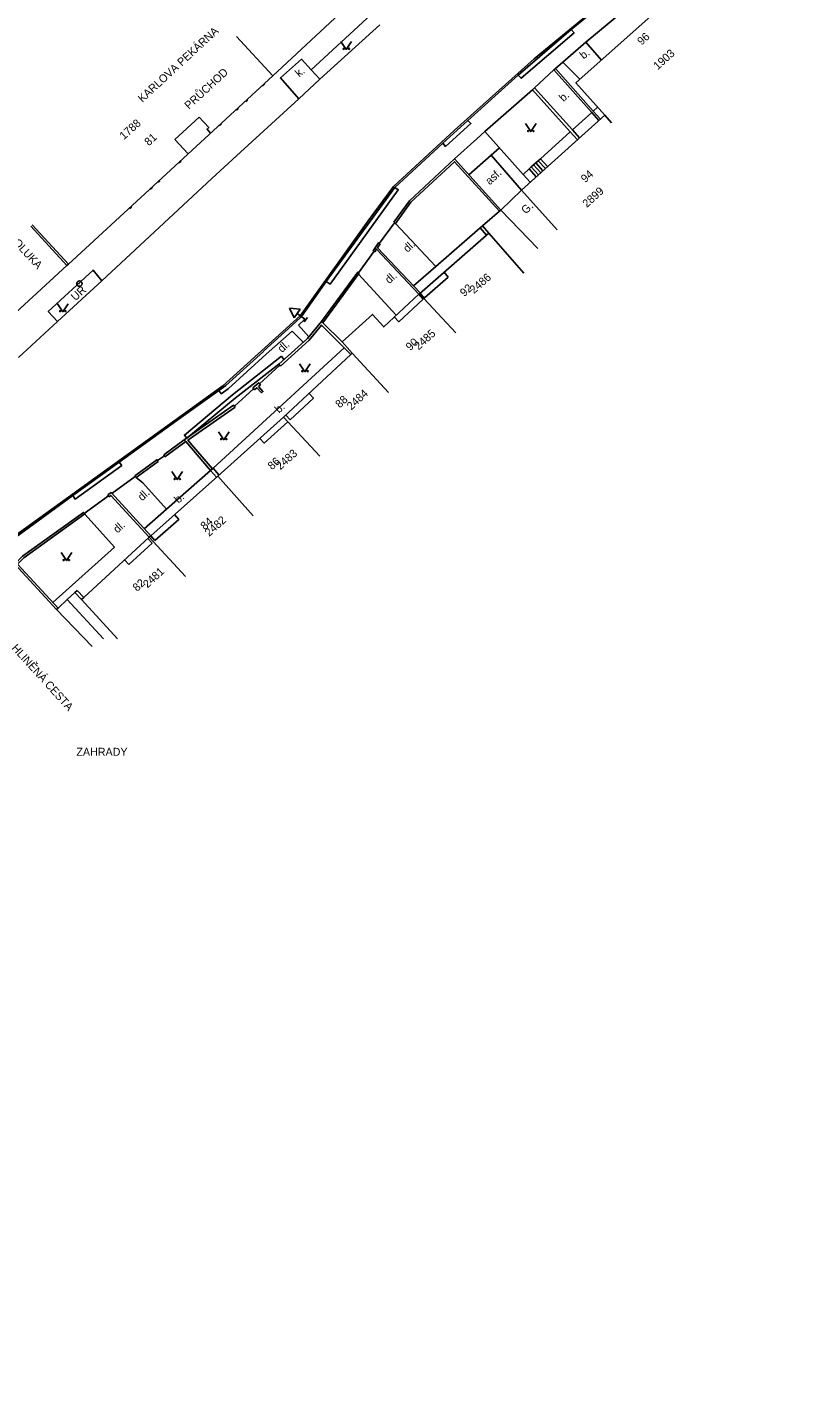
# Model space of a CAD drawing. Extents: x -584400 to -581602, y -1210894 to -1208793.
# Drawn here: x -582319.7 to -582247, y -1209460.2 to -1209333 of the extents above; entities that cross this region are included whole.
import ezdxf

# ---------------------------------------------------------------- set-up
doc = ezdxf.new("R2010")
doc.units = 0
for name, color, linetype in [('BUDOVY_MĚŘ', 7, 'Continuous'), ('POMOC_POPIS', 7, 'Continuous'), ('ROZHRANÍ_PLOCH', 7, 'Continuous'), ('ZN_DOPLŇKOVÉ', 7, 'Continuous'), ('ZN_KULTUR', 7, 'Continuous'), ('Č_POPIS_EVID', 7, 'Continuous')]:
    doc.layers.add(name, color=color, linetype=linetype)

msp = doc.modelspace()

# ---------------------------------------------------------------- linework, layer by layer
at = {"layer": 'BUDOVY_MĚŘ'}
for points in [[(-582265.6, -1209341.22), (-582268.3, -1209338.21), (-582257.05, -1209328.13), (-582254.27, -1209331.2)], [(-582287.76, -1209329.21), (-582296.71, -1209337.53)], [(-582300.1, -1209333.85), (-582296.71, -1209337.53)], [(-582296.71, -1209337.53), (-582315.86, -1209355.19)], [(-582265.6, -1209341.22), (-582273.4, -1209348.25)], [(-582264.96, -1209341.94), (-582265.6, -1209341.22)], [(-582271.88, -1209353.72), (-582275.35, -1209350.12), (-582273.4, -1209348.25)], [(-582270.06, -1209351.97), (-582273.4, -1209348.25)], [(-582319.25, -1209351.51), (-582315.86, -1209355.19)], [(-582273.18, -1209356.05), (-582276.47, -1209352.28), (-582282.96, -1209357.96)], [(-582282.96, -1209357.96), (-582283.03, -1209358.02), (-582286.31, -1209361.07), (-582287.36, -1209359.9), (-582290.22, -1209362.48)], [(-582279.57, -1209361.63), (-582282.96, -1209357.96)], [(-582289.26, -1209363.55), (-582290.22, -1209362.48)], [(-582295.7, -1209369.52), (-582289.38, -1209363.66), (-582289.26, -1209363.55)], [(-582285.86, -1209367.21), (-582289.26, -1209363.55)], [(-582301.87, -1209375.05), (-582295.7, -1209369.52)], [(-582292.3, -1209373.19), (-582295.7, -1209369.52)], [(-582308.29, -1209380.79), (-582308.15, -1209380.66), (-582301.87, -1209375.05)], [(-582301.87, -1209375.05), (-582298.54, -1209378.77)], [(-582308.29, -1209380.79), (-582314.42, -1209386.44), (-582314.64, -1209386.64)], [(-582304.9, -1209384.46), (-582308.29, -1209380.79)], [(-582311.25, -1209390.32), (-582314.64, -1209386.64)]]:
    msp.add_lwpolyline(points, dxfattribs=at)
at = {"layer": 'ROZHRANÍ_PLOCH'}
for points in [[(-582411.27, -1209460.15), (-582406.62, -1209456.16), (-582403.59, -1209453.59), (-582391.95, -1209443.5), (-582374.01, -1209428.06), (-582365.14, -1209420.28), (-582352.37, -1209408.95), (-582339.06, -1209397), (-582326.13, -1209385.36), (-582321.21, -1209380.9), (-582313.38, -1209375.25), (-582301.4, -1209366.6), (-582294.11, -1209360), (-582287.76, -1209351.14), (-582285.39, -1209347.91), (-582279.69, -1209342.63), (-582272.21, -1209335.94), (-582264.86, -1209329.84), (-582259.42, -1209325.45), (-582254.82, -1209321.63), (-582249.41, -1209317.62), (-582247.49, -1209316.56)], [(-582268.74, -1209333.19), (-582254.73, -1209321.75), (-582249.32, -1209317.74), (-582247.41, -1209316.69), (-582247.04, -1209316.55)], [(-582258.44, -1209326.96), (-582267.37, -1209334.39)], [(-582287.5, -1209331.8), (-582293.1, -1209336.97)], [(-582286.68, -1209332.75), (-582292.29, -1209337.84)], [(-582273.71, -1209337.48), (-582273.44, -1209337.76), (-582268.48, -1209333.51), (-582268.74, -1209333.19)], [(-582268.74, -1209333.19), (-582273.71, -1209337.48)], [(-582269.54, -1209336.27), (-582267.37, -1209334.39)], [(-582265.92, -1209336.08), (-582267.37, -1209334.39)], [(-582293.1, -1209336.97), (-582294.01, -1209335.98), (-582295.99, -1209337.74), (-582294.28, -1209339.69)], [(-582270.21, -1209336.85), (-582269.54, -1209336.27)], [(-582267.92, -1209337.87), (-582269.54, -1209336.27)], [(-582293.1, -1209336.97), (-582292.29, -1209337.84)], [(-582278.43, -1209341.72), (-582273.71, -1209337.48)], [(-582270.36, -1209336.97), (-582272.18, -1209338.67)], [(-582270.21, -1209336.85), (-582270.36, -1209336.97)], [(-582266.82, -1209340.97), (-582270.36, -1209336.97)], [(-582266.68, -1209340.84), (-582270.21, -1209336.85)], [(-582297.7, -1209338.45), (-582297.66, -1209338.5)], [(-582297.56, -1209338.31), (-582297.51, -1209338.36), (-582297.66, -1209338.5)], [(-582292.29, -1209337.84), (-582294.28, -1209339.69)], [(-582272.37, -1209338.84), (-582276.84, -1209342.75)], [(-582272.37, -1209338.84), (-582272.18, -1209338.67)], [(-582268.83, -1209342.78), (-582272.37, -1209338.84)], [(-582268.64, -1209342.61), (-582272.18, -1209338.67)], [(-582294.28, -1209339.69), (-582300.1, -1209345.03), (-582302.43, -1209347.16), (-582312.73, -1209356.74)], [(-582299.28, -1209339.9), (-582299.23, -1209339.95)], [(-582299.13, -1209339.77), (-582299.09, -1209339.82), (-582299.23, -1209339.95)], [(-582303.6, -1209341.42), (-582305.88, -1209343.51), (-582304.65, -1209344.85)], [(-582303.6, -1209341.42), (-582302.71, -1209342.38), (-582302.87, -1209342.53), (-582302.53, -1209342.9)], [(-582300.15, -1209340.71), (-582300.11, -1209340.76)], [(-582300.01, -1209340.57), (-582299.96, -1209340.62), (-582300.11, -1209340.76)], [(-582266.82, -1209340.97), (-582268.64, -1209342.61)], [(-582266.15, -1209341.72), (-582266.82, -1209340.97)], [(-582266.27, -1209340.48), (-582266.68, -1209340.84)], [(-582266.01, -1209341.59), (-582266.68, -1209340.84)], [(-582301.74, -1209342.17), (-582301.69, -1209342.22)], [(-582301.59, -1209342.03), (-582301.54, -1209342.08), (-582301.69, -1209342.22)], [(-582278.43, -1209341.72), (-582280.77, -1209343.86)], [(-582280.77, -1209343.86), (-582280.51, -1209344.15), (-582278.15, -1209342), (-582278.43, -1209341.72)], [(-582277.58, -1209343.45), (-582276.84, -1209342.75)], [(-582276.84, -1209342.75), (-582273.26, -1209346.78)], [(-582268.83, -1209342.78), (-582271.63, -1209345.31)], [(-582268.16, -1209343.53), (-582268.83, -1209342.78)], [(-582267.97, -1209343.35), (-582268.64, -1209342.61)], [(-582285.27, -1209348), (-582280.77, -1209343.86)], [(-582277.58, -1209343.45), (-582279.68, -1209345.33)], [(-582278.34, -1209346.82), (-582275.47, -1209344.3)], [(-582273.4, -1209348.25), (-582276.25, -1209344.98)], [(-582271.63, -1209345.31), (-582271.84, -1209345.5)], [(-582270.96, -1209346.05), (-582271.63, -1209345.31)], [(-582305.51, -1209345.65), (-582305.47, -1209345.7)], [(-582305.37, -1209345.51), (-582305.32, -1209345.56), (-582305.47, -1209345.7)], [(-582272.69, -1209346.26), (-582273.26, -1209346.78)], [(-582272.49, -1209346.08), (-582272.69, -1209346.26)], [(-582272.02, -1209347), (-582272.69, -1209346.26)], [(-582272.27, -1209345.88), (-582272.49, -1209346.08)], [(-582271.82, -1209346.82), (-582272.49, -1209346.08)], [(-582272.06, -1209345.69), (-582272.27, -1209345.88)], [(-582271.6, -1209346.63), (-582272.27, -1209345.88)], [(-582271.84, -1209345.5), (-582272.06, -1209345.69)], [(-582271.39, -1209346.44), (-582272.06, -1209345.69)], [(-582271.17, -1209346.24), (-582271.84, -1209345.5)], [(-582307.49, -1209347.47), (-582307.44, -1209347.52)], [(-582307.34, -1209347.34), (-582307.3, -1209347.39), (-582307.44, -1209347.52)], [(-582273.26, -1209346.78), (-582272.6, -1209347.52)], [(-582308.2, -1209348.13), (-582308.16, -1209348.18)], [(-582308.06, -1209347.99), (-582308.01, -1209348.05), (-582308.16, -1209348.18)], [(-582291.7, -1209356.83), (-582291.34, -1209357.07), (-582284.95, -1209348.22), (-582285.27, -1209348)], [(-582285.27, -1209348), (-582291.7, -1209356.83)], [(-582310.15, -1209349.92), (-582310.1, -1209349.98)], [(-582310.01, -1209349.79), (-582309.96, -1209349.84), (-582310.1, -1209349.98)], [(-582275.48, -1209350.24), (-582277.07, -1209351.59)], [(-582285.22, -1209351.37), (-582281.44, -1209355.41)], [(-582277.29, -1209351.78), (-582277.07, -1209351.59)], [(-582276.47, -1209352.28), (-582277.07, -1209351.59)], [(-582281.44, -1209355.41), (-582277.29, -1209351.78)], [(-582276.68, -1209352.47), (-582277.29, -1209351.78)], [(-582316, -1209355.31), (-582320.8, -1209359.72)], [(-582283.52, -1209357.23), (-582281.44, -1209355.41)], [(-582312.73, -1209356.74), (-582313.55, -1209355.75), (-582317.75, -1209359.62), (-582316.89, -1209360.58)], [(-582312.73, -1209356.74), (-582316.89, -1209360.58)], [(-582288.67, -1209356.13), (-582285.15, -1209359.98)], [(-582280.26, -1209356.41), (-582282.49, -1209358.36), (-582282.89, -1209357.9)], [(-582280.26, -1209356.41), (-582280.66, -1209355.95)], [(-582294.01, -1209360.11), (-582291.7, -1209356.83)], [(-582282.61, -1209358.46), (-582283.03, -1209358.02)], [(-582282.61, -1209358.46), (-582284.9, -1209360.59), (-582285.32, -1209360.14)], [(-582316.89, -1209360.58), (-582320.52, -1209363.93)], [(-582297.58, -1209363.36), (-582294.57, -1209360.62), (-582294.01, -1209360.11)], [(-582294.3, -1209360.91), (-582293.73, -1209360.39), (-582294.01, -1209360.11)], [(-582297.32, -1209363.63), (-582294.89, -1209361.47)], [(-582293.87, -1209362.52), (-582294.89, -1209361.47)], [(-582294.3, -1209360.91), (-582293.33, -1209361.99)], [(-582302.31, -1209374.3), (-582290.01, -1209363.03)], [(-582304.77, -1209371.49), (-582304.99, -1209371.21), (-582300.47, -1209367.43), (-582295.9, -1209363.82)], [(-582301.76, -1209367.04), (-582301.12, -1209366.57), (-582297.58, -1209363.38)], [(-582297.32, -1209363.63), (-582300.89, -1209366.89)], [(-582295.66, -1209364.13), (-582295.9, -1209363.82)], [(-582304.77, -1209371.49), (-582300.23, -1209367.75), (-582296.14, -1209364.57)], [(-582301.76, -1209367.04), (-582301.53, -1209367.34), (-582300.89, -1209366.89)], [(-582311.09, -1209373.74), (-582305.7, -1209369.85), (-582301.76, -1209367.04)], [(-582295.09, -1209369.77), (-582292.9, -1209367.75), (-582293.31, -1209367.31)], [(-582295.09, -1209369.77), (-582295.5, -1209369.34)], [(-582295.29, -1209369.97), (-582297.53, -1209371.97), (-582297.93, -1209371.52)], [(-582311.09, -1209373.74), (-582315.45, -1209376.88)], [(-582315.45, -1209376.88), (-582315.23, -1209377.21), (-582310.86, -1209374.06)], [(-582311.09, -1209373.74), (-582310.86, -1209374.06)], [(-582306.68, -1209378.15), (-582302.56, -1209374.52)], [(-582302.56, -1209374.52), (-582302.31, -1209374.3)], [(-582301.99, -1209375.15), (-582302.56, -1209374.52)], [(-582301.75, -1209374.94), (-582302.31, -1209374.3)], [(-582309.52, -1209375.19), (-582308.9, -1209375.69), (-582306.68, -1209378.15)], [(-582325.08, -1209384.63), (-582321.12, -1209381.02), (-582315.45, -1209376.88)], [(-582306.68, -1209378.15), (-582308.77, -1209379.99)], [(-582317.31, -1209386.9), (-582311.55, -1209381.71), (-582314.29, -1209378.66)], [(-582307.75, -1209381.11), (-582305.52, -1209379.12), (-582305.92, -1209378.67)], [(-582310.19, -1209383.36), (-582308.02, -1209381.35), (-582308.42, -1209380.91)], [(-582307.75, -1209381.11), (-582308.15, -1209380.66)], [(-582310.19, -1209383.36), (-582310.6, -1209382.92)], [(-582312.57, -1209390.31), (-582315.97, -1209386.64)]]:
    msp.add_lwpolyline(points, dxfattribs=at)
at = {"layer": 'ZN_DOPLŇKOVÉ'}
for p, q in [((-582295.13, -1209359.31), (-582294.72, -1209360.22)), ((-582295.13, -1209359.31), (-582294.14, -1209359.41)), ((-582294.72, -1209360.22), (-582294.14, -1209359.41)), ((-582293.62, -1209360.4), (-582294.43, -1209359.82)), ((-582293.77, -1209360.6), (-582293.47, -1209360.2))]:
    msp.add_line(p, q, dxfattribs=at)
for points in [[(-582285.37, -1209351.26), (-582283.9, -1209349.26), (-582279.68, -1209345.33), (-582275.35, -1209350.12)], [(-582275.48, -1209350.24), (-582279.69, -1209345.59), (-582283.77, -1209349.38), (-582285.22, -1209351.37)], [(-582275.48, -1209350.24), (-582275.35, -1209350.12)], [(-582316, -1209355.31), (-582319.38, -1209351.64)], [(-582285.29, -1209351.32), (-582286.72, -1209353.24)], [(-582285.37, -1209351.26), (-582285.22, -1209351.37)], [(-582287.22, -1209353.99), (-582288.68, -1209356)], [(-582287.12, -1209353.67), (-582287.3, -1209353.94), (-582287.15, -1209354.04)], [(-582287.15, -1209354.04), (-582286.99, -1209353.8)], [(-582286.99, -1209353.8), (-582287.12, -1209353.67), (-582286.8, -1209353.19), (-582286.65, -1209353.29)], [(-582283.03, -1209358.02), (-582286.99, -1209353.8)], [(-582286.65, -1209353.29), (-582286.89, -1209353.65), (-582282.9, -1209357.89)], [(-582316, -1209355.31), (-582315.86, -1209355.19)], [(-582292.14, -1209360.56), (-582288.75, -1209355.95), (-582288.61, -1209356.05)], [(-582288.61, -1209356.05), (-582292.01, -1209360.69)], [(-582296.14, -1209364.57), (-582293.47, -1209362.16), (-582292.14, -1209360.56), (-582292.01, -1209360.69)], [(-582289.38, -1209363.66), (-582292.13, -1209360.91), (-582293.3, -1209362.33), (-582295.98, -1209364.74)], [(-582292.01, -1209360.69), (-582290.22, -1209362.48)], [(-582296.06, -1209364.66), (-582297.95, -1209366.4)], [(-582296.14, -1209364.57), (-582295.98, -1209364.74)], [(-582298.51, -1209366.89), (-582300.31, -1209368.51)], [(-582298.59, -1209366.8), (-582298.03, -1209366.31), (-582297.87, -1209366.49)], [(-582298.59, -1209366.8), (-582298.43, -1209366.98)], [(-582297.77, -1209367.26), (-582298.2, -1209366.77), (-582298.43, -1209366.98)], [(-582297.87, -1209366.49), (-582298.06, -1209366.65)], [(-582298.06, -1209366.65), (-582297.63, -1209367.13), (-582297.77, -1209367.26)], [(-582304.87, -1209371.82), (-582305.01, -1209371.66), (-582300.38, -1209368.41), (-582300.24, -1209368.6)], [(-582300.24, -1209368.6), (-582304.66, -1209371.7), (-582302.38, -1209374.36)], [(-582306.93, -1209373.07), (-582305.01, -1209371.66)], [(-582304.87, -1209371.82), (-582306.81, -1209373.24)], [(-582302.56, -1209374.52), (-582304.87, -1209371.82)], [(-582306.87, -1209373.15), (-582307.51, -1209373.61)], [(-582306.93, -1209373.07), (-582306.81, -1209373.24)], [(-582309.65, -1209375.02), (-582307.57, -1209373.53), (-582307.45, -1209373.7)], [(-582307.45, -1209373.7), (-582309.52, -1209375.19)], [(-582309.59, -1209375.1), (-582311.78, -1209376.69)], [(-582309.65, -1209375.02), (-582309.52, -1209375.19)], [(-582312.1, -1209376.91), (-582314.37, -1209378.56)], [(-582312.16, -1209376.83), (-582311.85, -1209376.61), (-582308.15, -1209380.66)], [(-582312.16, -1209376.83), (-582312.05, -1209376.99)], [(-582308.29, -1209380.79), (-582311.88, -1209376.87), (-582312.05, -1209376.99)], [(-582316.96, -1209387.56), (-582320.88, -1209383.3), (-582320.16, -1209382.57), (-582314.44, -1209378.46), (-582314.33, -1209378.61)], [(-582314.33, -1209378.61), (-582320.04, -1209382.71), (-582320.62, -1209383.3), (-582316.82, -1209387.43)], [(-582314.33, -1209378.61), (-582314.29, -1209378.66)], [(-582315.26, -1209385.97), (-582315.97, -1209386.64)], [(-582314.64, -1209386.64), (-582315.26, -1209385.97), (-582315.04, -1209385.77)], [(-582314.42, -1209386.44), (-582315.04, -1209385.77)], [(-582315.97, -1209386.64), (-582316.82, -1209387.43)], [(-582316.82, -1209387.43), (-582316.96, -1209387.56), (-582313.63, -1209391.04)]]:
    msp.add_lwpolyline(points, dxfattribs=at)
for radius in [0.25, 0.0005]:
    msp.add_circle((-582314.83, -1209357.02), radius, dxfattribs=at)
at = {"layer": 'ZN_KULTUR'}
for points in [[(-582290.32, -1209334.31), (-582289.82, -1209335.06), (-582289.32, -1209334.31)], [(-582273.04, -1209342.02), (-582272.54, -1209342.77), (-582272.04, -1209342.02)], [(-582316.89, -1209358.9), (-582316.39, -1209359.65), (-582315.89, -1209358.9)], [(-582294.19, -1209364.52), (-582293.69, -1209365.27), (-582293.19, -1209364.52)], [(-582301.8, -1209370.9), (-582301.3, -1209371.65), (-582300.8, -1209370.9)], [(-582306.16, -1209374.63), (-582305.66, -1209375.38), (-582305.16, -1209374.63)], [(-582316.55, -1209382.23), (-582316.05, -1209382.98), (-582315.55, -1209382.23)]]:
    msp.add_lwpolyline(points, dxfattribs=at)
for centre in [(-582290.07, -1209335.01), (-582289.57, -1209335.01), (-582272.79, -1209342.72), (-582272.29, -1209342.72), (-582316.64, -1209359.6), (-582316.14, -1209359.6), (-582293.94, -1209365.22), (-582293.44, -1209365.22), (-582301.55, -1209371.6), (-582301.05, -1209371.6), (-582305.91, -1209375.33), (-582305.41, -1209375.33), (-582316.3, -1209382.93), (-582315.8, -1209382.93)]:
    msp.add_circle(centre, 0.05, dxfattribs=at)

# ---------------------------------------------------------------- texts
at = {"layer": 'POMOC_POPIS'}
for s, rotation, p in [('KARLOVA PEKÁRNA', 42.6697, (-582308.93, -1209340.08)), ('b.', 38.2202, (-582267.59, -1209336.02)), ('PRŮCHOD', 42.6697, (-582304.56, -1209340.73)), ('k.', 41.522, (-582294.22, -1209337.7)), ('b.', 42.8206, (-582269.47, -1209340.01)), ('asf.', 42.8206, (-582276.38, -1209347.81)), ('G.', 43.8572, (-582273, -1209350.55)), ('PROLUKA', 312.6738, (-582322.02, -1209352.19)), ('dl.', 42.8206, (-582284.08, -1209354.14)), ('dl.', 42.8206, (-582285.79, -1209357.08)), ('UR', 42.6016, (-582315.2, -1209358.68)), ('dl.', 42.8206, (-582295.84, -1209363.53)), ('b.', 42.8206, (-582296.12, -1209369.21)), ('dl.', 42.8206, (-582308.95, -1209377.43)), ('b.', 42.8206, (-582305.54, -1209377.66)), ('dl.', 42.8206, (-582311.25, -1209380.45)), ('HLINĚNÁ CESTA', 312.1712, (-582321.23, -1209391.22))]:
    msp.add_text(s, height=0.75, rotation=rotation, dxfattribs=at).set_placement(p)
msp.add_text('ZAHRADY', height=0.75, dxfattribs=at).set_placement((-582315.11, -1209401.28))
at = {"layer": 'Č_POPIS_EVID'}
for s, rotation, p in [('96', 41.8691, (-582262.15, -1209334.71)), ('1903', 41.8604, (-582260.64, -1209337.02)), ('1788', 41.8604, (-582310.66, -1209343.57)), ('81', 42.673, (-582308.32, -1209344.15)), ('94', 42.0259, (-582267.43, -1209347.6)), ('2899', 41.8604, (-582267.28, -1209349.93)), ('2486', 41.1454, (-582277.86, -1209358)), ('92', 41.1454, (-582278.77, -1209358.28)), ('2485', 42.1386, (-582283.04, -1209363.28)), ('90', 42.1386, (-582283.84, -1209363.35)), ('2484', 42.8513, (-582289.35, -1209368.92)), ('88', 42.8513, (-582290.43, -1209368.73)), ('86', 41.8185, (-582296.78, -1209374.52)), ('2483', 41.8185, (-582296, -1209374.52)), ('84', 41.8092, (-582303.08, -1209380.15)), ('2482', 41.8092, (-582302.67, -1209380.77)), ('82', 42.691, (-582309.42, -1209385.92)), ('2481', 42.691, (-582308.45, -1209385.6))]:
    msp.add_text(s, height=0.75, rotation=rotation, dxfattribs=at).set_placement(p)

doc.saveas('drawing.dxf')
